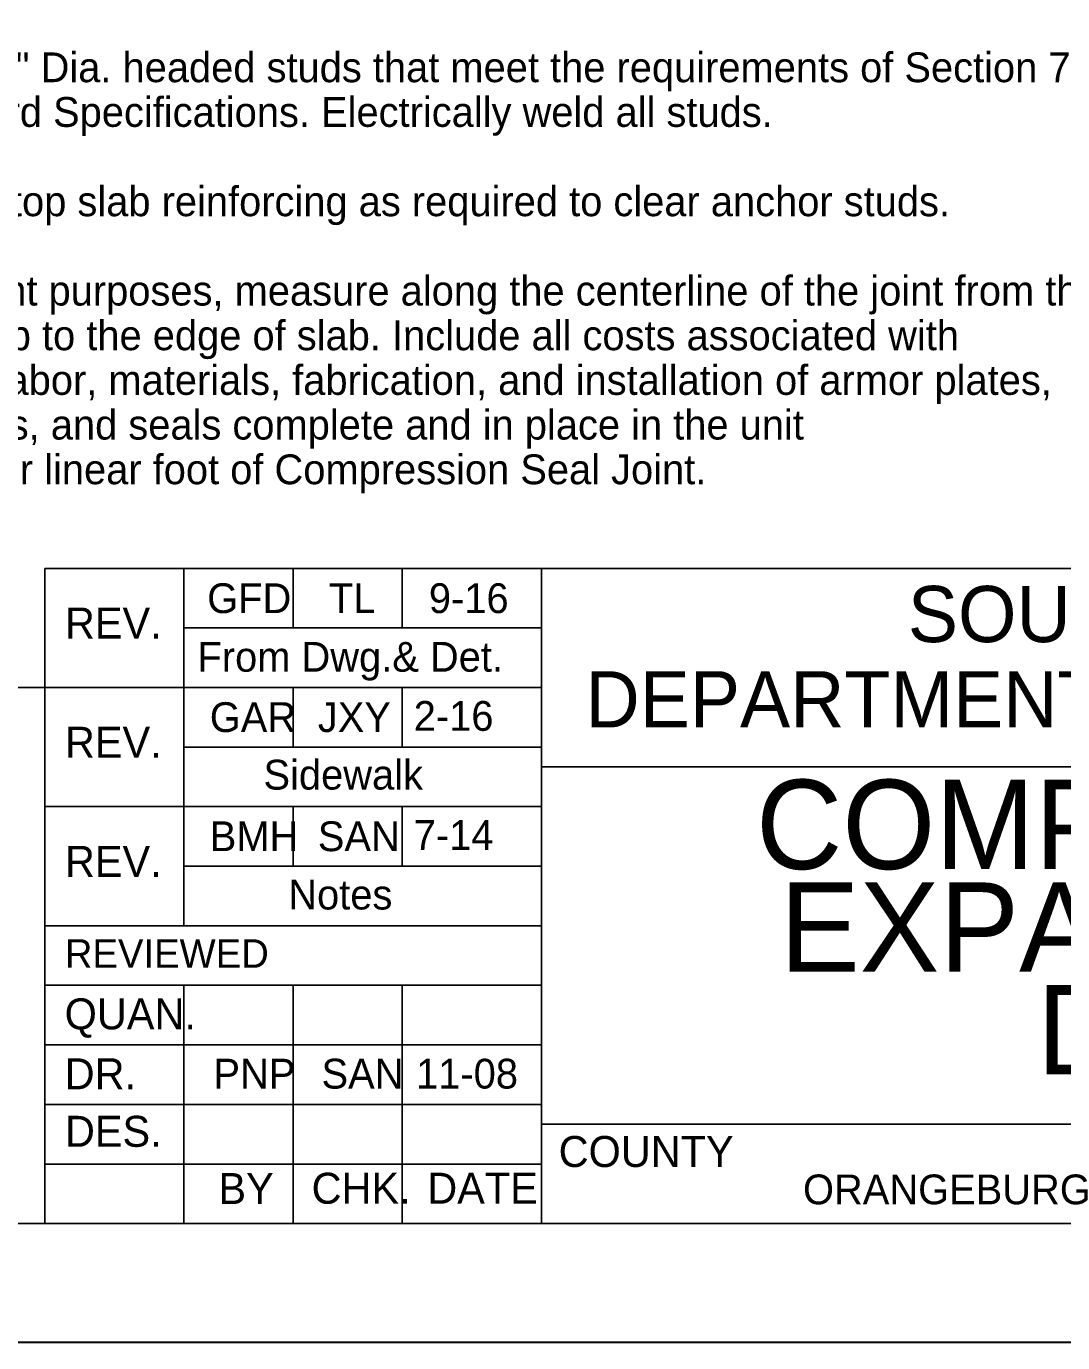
# Model space of a CAD drawing. Extents: x 3.7 to 39.9, y -2.3 to 19.7.
# Drawn here: x 31.66 to 36.01, y -2.32 to 3.21 of the extents above; entities that cross this region are included whole.
import ezdxf

# ---------------------------------------------------------------- set-up
doc = ezdxf.new("R2010")
doc.units = 0
for name, color, linetype in [('BR_BORDER LINES', 7, 'Continuous'), ('BR_TEXT', 7, 'Continuous'), ('RD_SHT_IplotShp', 7, 'Continuous')]:
    doc.layers.add(name, color=color, linetype=linetype)

msp = doc.modelspace()

# ---------------------------------------------------------------- linework, layer by layer
at = {"layer": 'BR_BORDER LINES'}
for p, q in [((31.7364, -1.817), (31.7364, 0.933)), ((31.7364, 0.933), (39.2364, 0.933)), ((32.3198, 0.933), (32.3198, -0.567)), ((32.7781, 0.683), (32.7781, 0.933)), ((33.2364, 0.683), (33.2364, 0.933)), ((33.8198, -1.817), (33.8198, 0.933)), ((32.3198, 0.683), (33.8198, 0.683)), ((29.4239, 0.433), (31.7364, 0.433)), ((31.7364, 0.433), (33.8198, 0.433)), ((32.7781, 0.183), (32.7781, 0.433)), ((33.2364, 0.183), (33.2364, 0.433)), ((32.3198, 0.183), (33.8198, 0.183)), ((33.8198, 0.0997), (39.2364, 0.0997)), ((33.8198, 0.0997), (33.8198, 0.0997)), ((31.7364, -0.067), (33.8198, -0.067)), ((32.7781, -0.317), (32.7781, -0.067)), ((33.2364, -0.317), (33.2364, -0.067)), ((32.3198, -0.317), (33.8198, -0.317)), ((31.7364, -0.567), (33.8198, -0.567)), ((31.7364, -0.817), (33.8198, -0.817)), ((32.3198, -0.817), (32.3198, -1.817)), ((32.7781, -0.817), (32.7781, -1.817)), ((33.2364, -0.817), (33.2364, -1.817)), ((31.7364, -1.067), (33.8198, -1.067)), ((31.7364, -1.317), (33.8198, -1.317)), ((33.8198, -1.4003), (39.2364, -1.4003)), ((31.7364, -1.567), (33.8198, -1.567)), ((5.5698, -1.817), (39.2364, -1.817)), ((3.7365, -2.3155), (39.7365, -2.3155))]:
    msp.add_line(p, q, dxfattribs=at)
at = {"layer": 'RD_SHT_IplotShp'}
msp.add_lwpolyline([(3.7365, 19.6831), (39.7365, 19.6831), (39.7365, -2.3169), (3.7365, -2.3169)], close=True, dxfattribs=at)

# ---------------------------------------------------------------- texts
at = {"layer": 'BR_TEXT'}
for s, height, p in [('Provide 1/2" Dia. headed studs that meet the requirements of Section 709 of', 0.125, (30.7676, 2.9739)), ('the Standard Specifications. Electrically weld all studs.', 0.125, (30.7676, 2.7864)), ('Field bend top slab reinforcing as required to clear anchor studs.', 0.125, (30.7676, 2.4114)), ('For payment purposes, measure along the centerline of the joint from the', 0.125, (30.7676, 2.0364)), ('edge of slab to the edge of slab. Include all costs associated with', 0.125, (30.7676, 1.8489)), ('furnishing labor, materials, fabrication, and installation of armor plates,', 0.125, (30.7676, 1.6614)), ('cover plates, and seals complete and in place in the unit', 0.125, (30.7676, 1.4739)), ('price bid per linear foot of Compression Seal Joint.', 0.125, (30.7676, 1.2864)), ('GFD', 0.125, (32.4178, 0.7455)), ('TL', 0.125, (32.9285, 0.7455)), ('9-16', 0.125, (33.3478, 0.7455)), ('SOUTH CAROLINA', 0.235852, (35.3572, 0.6235)), ('REV.', 0.13, (31.8211, 0.6384)), ('From Dwg.& Det.', 0.125, (32.3771, 0.4994)), ('DEPARTMENT  OF  TRANSPORTATION', 0.235852, (34.0046, 0.2658)), ('GAR', 0.125, (32.4287, 0.2462)), ('JXY', 0.125, (32.882, 0.2462)), ('2-16', 0.125, (33.2842, 0.2513)), ('REV.', 0.13, (31.8211, 0.1384)), ('Sidewalk', 0.125, (32.654, 0.0047)), ('COMPRESSION SEAL', 0.375, (34.7201, -0.329)), ('BMH', 0.125, (32.4287, -0.2538)), ('SAN', 0.125, (32.882, -0.2538)), ('7-14', 0.125, (33.2842, -0.2487)), ('REV.', 0.13, (31.8211, -0.3616)), ('Notes', 0.125, (32.758, -0.4987)), ('EXPANSION JOINT', 0.375, (34.8205, -0.7601)), ('REVIEWED', 0.12, (31.8205, -0.7435)), ('DETAILS', 0.375, (35.8982, -1.1912)), ('QUAN.', 0.13, (31.8199, -1.0018)), ('DR.', 0.13, (31.82, -1.2533)), ('PNP', 0.125, (32.4442, -1.2502)), ('SAN', 0.125, (32.8975, -1.2503)), ('11-08', 0.125, (33.2941, -1.2503)), ('DES.', 0.13, (31.8211, -1.4947)), ('COUNTY', 0.13, (33.8923, -1.5795)), ('CHK.', 0.13, (32.8559, -1.7337)), ('BY', 0.13, (32.4651, -1.735)), ('DATE', 0.13, (33.3411, -1.7336)), ('ORANGEBURG', 0.125, (34.9173, -1.7361))]:
    msp.add_text(s, height=height, dxfattribs=at).set_placement(p)

doc.saveas('drawing.dxf')
